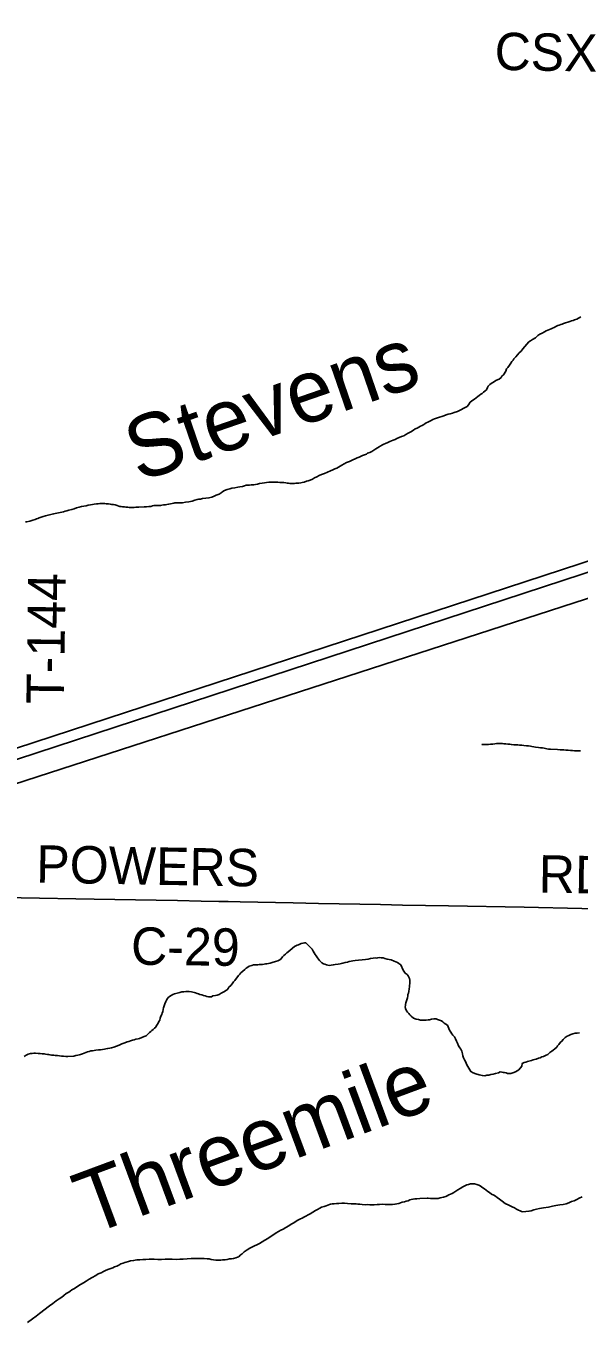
# Model space of a CAD drawing. Extents: x -483 to 680, y 0 to 440.
# Drawn here: x 79.4 to 121.3, y 248.8 to 347.1 of the extents above; entities that cross this region are included whole.
import ezdxf

# ---------------------------------------------------------------- set-up
doc = ezdxf.new("R2010")
doc.units = 0
for name, color, linetype in [('GM_X_County_Road', 7, 'Continuous'), ('GM_X_County_Road_Text', 7, 'Continuous'), ('GM_X_Minor_River', 7, 'Continuous'), ('GM_X_Minor_River_Text', 7, 'Continuous'), ('GM_X_Rail_Line', 7, 'Continuous'), ('GM_X_Rail_Line_Text', 7, 'Continuous'), ('GM_X_Township_Road_Text', 7, 'Continuous'), ('GM_X_US_Route', 7, 'Continuous')]:
    doc.layers.add(name, color=color, linetype=linetype)

msp = doc.modelspace()

# ---------------------------------------------------------------- linework, layer by layer
at = {"layer": 'GM_X_County_Road'}
msp.add_lwpolyline([(77.163, 281.006), (79.053, 280.972), (84.585, 280.875), (89.278, 280.783), (90.894, 280.761), (92.697, 280.726), (94.033, 280.704), (94.748, 280.692), (95.649, 280.674), (99.658, 280.588), (101.585, 280.553), (106.278, 280.468), (107.954, 280.425), (111.436, 280.37), (117.186, 280.256), (121.537, 280.166), (124.893, 280.092), (126.566, 280.056)], dxfattribs=at)
at = {"layer": 'GM_X_Minor_River'}
for points in [[(121.003, 324.791), (120.887, 324.737), (120.754, 324.702), (120.639, 324.667), (120.485, 324.614), (120.313, 324.561), (120.16, 324.508), (120.045, 324.473), (119.949, 324.438), (119.834, 324.384), (119.738, 324.348), (119.584, 324.276), (119.449, 324.204), (119.316, 324.169), (119.219, 324.115), (119.104, 324.061), (118.97, 324.007), (118.854, 323.953), (118.72, 323.881), (118.546, 323.79), (118.373, 323.7), (118.2, 323.59), (118.024, 323.424), (117.812, 323.296), (117.658, 323.186), (117.523, 323.114), (117.386, 322.946), (117.229, 322.76), (117.073, 322.594), (116.936, 322.426), (116.799, 322.278), (116.663, 322.129), (116.545, 321.98), (116.389, 321.832), (116.33, 321.739), (116.251, 321.627), (116.172, 321.515), (116.073, 321.347), (115.936, 321.179), (115.839, 321.087), (115.777, 320.899), (115.599, 320.618), (115.483, 320.507), (115.423, 320.414), (115.268, 320.304), (115.076, 320.214), (114.96, 320.141), (114.845, 320.068), (114.748, 320.013), (114.574, 319.885), (114.438, 319.756), (114.398, 319.662), (114.318, 319.493), (114.201, 319.382), (114.104, 319.308), (113.988, 319.216), (113.891, 319.162), (113.756, 319.051), (113.659, 318.978), (113.543, 318.886), (113.407, 318.776), (113.272, 318.703), (113.175, 318.611), (113.078, 318.537), (112.959, 318.35), (112.861, 318.22), (112.13, 317.84), (111.881, 317.77), (111.747, 317.717), (111.575, 317.664), (111.422, 317.63), (111.269, 317.577), (111.096, 317.524), (110.924, 317.472), (110.751, 317.4), (110.541, 317.33), (110.368, 317.277), (110.253, 317.223), (110.118, 317.151), (109.965, 317.079), (109.868, 317.024), (109.753, 316.97), (109.657, 316.916), (109.56, 316.842), (109.445, 316.788), (109.329, 316.734), (109.194, 316.643), (109.06, 316.589), (108.925, 316.517), (108.79, 316.425), (108.578, 316.298), (108.385, 316.189), (108.212, 316.098), (108.058, 316.007), (107.885, 315.935), (107.712, 315.864), (107.52, 315.793), (107.386, 315.72), (107.251, 315.667), (107.117, 315.613), (107.002, 315.559)], [(121.464, 325.007), (121.175, 324.843), (121.003, 324.791)], [(107.002, 315.559), (106.848, 315.487), (106.675, 315.416), (106.541, 315.362), (106.426, 315.308), (106.272, 315.217), (106.175, 315.163), (106.059, 315.09), (105.924, 314.998), (105.789, 314.907), (105.635, 314.816), (105.481, 314.744), (105.308, 314.672), (105.212, 314.618), (104.924, 314.511), (104.809, 314.457), (104.674, 314.384), (104.521, 314.331), (104.367, 314.259), (104.176, 314.188), (103.945, 314.061), (103.695, 313.973), (103.522, 313.863), (103.349, 313.773), (103.233, 313.7), (103.098, 313.627), (102.963, 313.555), (102.828, 313.482), (102.675, 313.41), (102.483, 313.339), (102.271, 313.231), (102.041, 313.141), (101.811, 313.052), (101.638, 312.981), (101.465, 312.89), (101.292, 312.8), (101.119, 312.709), (100.946, 312.638), (100.812, 312.584), (100.678, 312.55), (100.486, 312.479), (100.353, 312.463), (100.238, 312.428), (100.086, 312.413), (99.952, 312.397), (99.857, 312.4), (99.762, 312.383), (99.591, 312.387), (99.496, 312.39), (99.401, 312.392), (99.307, 312.414), (99.212, 312.416), (99.099, 312.438), (98.947, 312.461), (98.815, 312.464), (98.644, 312.469), (98.511, 312.472), (98.397, 312.475), (98.283, 312.478), (98.169, 312.481), (98.017, 312.485), (97.827, 312.489), (97.313, 312.408), (97.103, 312.375), (96.95, 312.341), (96.816, 312.306), (96.683, 312.291), (96.588, 312.293), (96.493, 312.277), (96.359, 312.261), (96.207, 312.246), (96.112, 312.248), (95.978, 312.195), (95.825, 312.161), (95.634, 312.128), (95.462, 312.094), (95.253, 312.061), (95.024, 312.029), (94.852, 311.977), (94.661, 311.925), (94.469, 311.853), (94.334, 311.781), (94.198, 311.67), (94.044, 311.579), (93.833, 311.49), (93.679, 311.418), (93.488, 311.347), (93.277, 311.295), (93.049, 311.263), (92.782, 311.232), (92.629, 311.198), (92.496, 311.182), (92.4, 311.165), (92.209, 311.113), (92.017, 311.042), (91.75, 310.992), (91.502, 310.96), (91.274, 310.928), (90.704, 310.905), (90.608, 310.888), (90.494, 310.872)], [(90.494, 310.872), (90.36, 310.838), (90.226, 310.803), (90.093, 310.788), (89.997, 310.771), (89.826, 310.756), (89.712, 310.74), (89.616, 310.705), (89.369, 310.711), (89.217, 310.715), (89.122, 310.717), (89.008, 310.682), (88.874, 310.648), (88.721, 310.633), (88.55, 310.618), (88.379, 310.622), (87.961, 310.595), (87.827, 310.579), (87.733, 310.582), (87.618, 310.566), (87.485, 310.55), (87.371, 310.553), (87.238, 310.556), (87.125, 310.578), (86.992, 310.582), (86.878, 310.604), (86.745, 310.607), (86.632, 310.629), (86.537, 310.631), (86.443, 310.672), (86.311, 310.713), (86.179, 310.754), (86.029, 310.796), (85.896, 310.799), (85.801, 310.821), (85.669, 310.843), (85.574, 310.846), (85.479, 310.848), (85.385, 310.869), (85.29, 310.872), (85.118, 310.857), (85.004, 310.86), (84.871, 310.844), (84.757, 310.828), (84.585, 310.814), (84.452, 310.779), (84.299, 310.764), (84.127, 310.73), (83.975, 310.696), (83.784, 310.663), (83.612, 310.63), (83.44, 310.596), (83.249, 310.525), (83.076, 310.472), (82.885, 310.42), (82.656, 310.369), (82.503, 310.316), (82.369, 310.281), (82.254, 310.246), (81.738, 310.126), (81.509, 310.075), (81.299, 310.043), (81.089, 309.991), (80.898, 309.939), (80.706, 309.868), (80.496, 309.816), (80.4, 309.781), (80.304, 309.726), (80.208, 309.691), (80.112, 309.655), (79.94, 309.602), (79.71, 309.532), (79.481, 309.481), (79.386, 309.465)], [(115.071, 292.658), (114.957, 292.642), (114.804, 292.627), (114.633, 292.613), (114.462, 292.598), (114.329, 292.583), (114.215, 292.585), (114.101, 292.588), (113.968, 292.592), (113.968, 292.592), (113.968, 292.592)], [(121.439, 292.115), (121.287, 292.119), (121.155, 292.122), (121.003, 292.126), (120.832, 292.131), (120.68, 292.135), (120.51, 292.158), (120.339, 292.162), (120.188, 292.185), (120.055, 292.189), (119.903, 292.193), (119.695, 292.217), (119.183, 292.249), (119.031, 292.253), (118.898, 292.275), (118.785, 292.297), (118.69, 292.319), (118.558, 292.341), (118.406, 292.345), (118.255, 292.368), (118.046, 292.392), (117.914, 292.415), (117.763, 292.437), (117.649, 292.459), (117.498, 292.482), (117.346, 292.486), (117.157, 292.51), (116.986, 292.533), (116.816, 292.538), (116.683, 292.56), (116.55, 292.564), (116.398, 292.567), (116.209, 292.591), (116.077, 292.614), (115.925, 292.618), (115.792, 292.64), (115.641, 292.644), (115.527, 292.666), (115.413, 292.669), (115.318, 292.671), (115.205, 292.674), (115.071, 292.658)], [(89.636, 272.001), (89.697, 272.132), (89.737, 272.245), (89.778, 272.339), (89.82, 272.528), (89.842, 272.622), (89.884, 272.773), (89.945, 272.943), (90.006, 273.112), (90.066, 273.224), (90.126, 273.337), (90.223, 273.429), (90.416, 273.576), (90.551, 273.649), (90.667, 273.703), (91.068, 273.806), (91.221, 273.841), (91.373, 273.856), (91.525, 273.871), (91.658, 273.867), (91.791, 273.864), (91.961, 273.841), (92.056, 273.819), (92.169, 273.797), (92.263, 273.757), (92.376, 273.716), (92.49, 273.694), (92.584, 273.654), (92.734, 273.612), (92.866, 273.571), (92.998, 273.529), (93.13, 273.488), (93.244, 273.466), (93.376, 273.463), (93.471, 273.46), (93.587, 273.533), (93.778, 273.567), (93.912, 273.601), (94.065, 273.654), (94.219, 273.745), (94.316, 273.8), (94.45, 273.872), (94.566, 273.945), (94.662, 274), (94.741, 274.093), (94.8, 274.186), (94.936, 274.316), (95.034, 274.446), (95.152, 274.595), (95.231, 274.707), (95.525, 275.079), (95.623, 275.191), (95.701, 275.284), (95.856, 275.413), (95.992, 275.542), (96.109, 275.634), (96.225, 275.726), (96.322, 275.8), (96.532, 275.851), (96.647, 275.886), (96.742, 275.884), (96.856, 275.9), (96.989, 275.897), (97.084, 275.913), (97.179, 275.911), (97.351, 275.925), (97.465, 275.941), (97.56, 275.958), (97.675, 275.974), (97.789, 275.99), (97.923, 276.025), (98.076, 276.059), (98.325, 276.147), (98.497, 276.2), (98.612, 276.254), (98.728, 276.327), (98.865, 276.494), (98.962, 276.587), (99.079, 276.698), (99.196, 276.809), (99.293, 276.882), (99.428, 276.993), (99.778, 277.288), (99.874, 277.342), (99.97, 277.378), (100.066, 277.413), (100.277, 277.503), (100.411, 277.537), (100.525, 277.553), (100.62, 277.551), (100.731, 277.453), (100.824, 277.356), (100.936, 277.258), (101.102, 277.083), (101.193, 276.929), (101.247, 276.813), (101.339, 276.678), (101.412, 276.562), (101.503, 276.427), (101.596, 276.311), (101.65, 276.214)], [(101.65, 276.214), (101.743, 276.136), (101.836, 276.039), (101.967, 275.978), (102.061, 275.938), (102.193, 275.897), (102.287, 275.875), (102.401, 275.853), (102.534, 275.869), (102.705, 275.883), (102.858, 275.918), (103.068, 275.931), (103.22, 275.965), (103.316, 276.001), (103.431, 276.017), (103.603, 276.069), (103.775, 276.103), (103.908, 276.138), (104.061, 276.172), (104.195, 276.206), (104.366, 276.221), (105.147, 276.296), (105.338, 276.329), (105.528, 276.362), (105.719, 276.395), (105.871, 276.41), (105.985, 276.407), (106.081, 276.424), (106.233, 276.439), (106.346, 276.417), (106.479, 276.414), (106.611, 276.372), (106.781, 276.33), (106.951, 276.288), (107.102, 276.265), (107.328, 276.164), (107.441, 276.123), (107.572, 276.063), (107.684, 275.984), (107.815, 275.886), (108.013, 275.482), (108.16, 275.269), (108.309, 275.151), (108.383, 275.054), (108.437, 274.958), (108.491, 274.843), (108.507, 274.728), (108.505, 274.615), (108.501, 274.482), (108.478, 274.33), (108.476, 274.217), (108.453, 274.065), (108.429, 273.876), (108.407, 273.744), (108.367, 273.65), (108.345, 273.536), (108.322, 273.385), (108.199, 273.008), (108.177, 272.895), (108.174, 272.8), (108.153, 272.705), (108.169, 272.572), (108.259, 272.399), (108.333, 272.302), (108.425, 272.205), (108.499, 272.108), (108.61, 271.991), (108.796, 271.853), (108.984, 271.773), (109.155, 271.749), (109.306, 271.707), (109.457, 271.704), (109.59, 271.7), (109.742, 271.696), (109.894, 271.711), (110.009, 271.727), (110.143, 271.762), (110.333, 271.795), (110.504, 271.791), (110.617, 271.75), (110.899, 271.647), (111.011, 271.569), (111.123, 271.471), (111.235, 271.392), (111.366, 271.313), (111.42, 271.178), (111.509, 270.948), (111.619, 270.794), (111.691, 270.659), (111.765, 270.562), (111.895, 270.445), (111.967, 270.291), (112.038, 270.099), (112.129, 269.945), (112.201, 269.753), (112.311, 269.598), (112.384, 269.501), (112.456, 269.348), (112.473, 269.252), (112.489, 269.138), (112.524, 269.004)], [(79.285, 268.941), (79.42, 269.051), (79.574, 269.123), (79.747, 269.176), (79.879, 269.172), (80.013, 269.188), (80.127, 269.185), (80.335, 269.18), (80.487, 269.176), (80.639, 269.153), (80.79, 269.149), (80.885, 269.128), (81.036, 269.105), (81.131, 269.084), (81.244, 269.062), (81.358, 269.04), (81.528, 269.036), (81.642, 269.014), (81.794, 269.01), (81.964, 268.986), (82.115, 268.964), (82.267, 268.96), (82.438, 268.936), (82.589, 268.933), (83.027, 268.959), (83.18, 269.013), (83.352, 269.046), (83.447, 269.063), (83.543, 269.098), (83.696, 269.151), (83.83, 269.186), (83.945, 269.24), (84.08, 269.294), (84.195, 269.329), (84.328, 269.363), (84.462, 269.379), (84.576, 269.395), (84.709, 269.41), (84.919, 269.443), (85.072, 269.458), (85.205, 269.474), (85.357, 269.489), (85.472, 269.524), (85.606, 269.559), (85.758, 269.574), (85.892, 269.608), (86.064, 269.661), (86.275, 269.731), (86.467, 269.803), (86.678, 269.911), (86.908, 269.981), (87.081, 270.053), (87.215, 270.087), (87.33, 270.141), (87.483, 270.176), (87.616, 270.21), (87.75, 270.245), (87.903, 270.279), (88.018, 270.314), (88.382, 270.456), (88.517, 270.51), (88.692, 270.677), (88.77, 270.769), (88.867, 270.843), (88.963, 270.917), (89.06, 270.99), (89.158, 271.101), (89.255, 271.175), (89.315, 271.287), (89.413, 271.418), (89.493, 271.606), (89.553, 271.699), (89.595, 271.85), (89.636, 272.001)], [(116.997, 268.217), (117.029, 268.414), (117.183, 268.486), (117.298, 268.521), (117.432, 268.574), (117.719, 268.643), (117.853, 268.677), (117.967, 268.712), (118.082, 268.747), (118.274, 268.819), (118.389, 268.853), (118.504, 268.908), (118.638, 268.942), (118.753, 268.996), (118.85, 269.051), (118.965, 269.105), (119.12, 269.234), (119.275, 269.344), (119.371, 269.417), (119.507, 269.527), (119.643, 269.657), (119.703, 269.75), (119.8, 269.843), (119.938, 270.029), (120.034, 270.103), (120.133, 270.233), (120.288, 270.381), (120.424, 270.472), (120.558, 270.545), (120.712, 270.617), (120.865, 270.651), (121.037, 270.704), (121.189, 270.719), (121.361, 270.733)], [(112.524, 269.004), (112.577, 268.851), (112.649, 268.678), (112.722, 268.562), (112.838, 268.309)], [(112.838, 268.309), (113.127, 267.803), (113.314, 267.702), (113.522, 267.638), (113.767, 267.554), (114.012, 267.489), (114.202, 267.482), (114.356, 267.515), (114.49, 267.53), (114.644, 267.582), (114.835, 267.613), (115.008, 267.665), (115.219, 267.715), (115.354, 267.767), (115.487, 267.763), (115.582, 267.741), (115.695, 267.718), (115.809, 267.695), (115.922, 267.653), (116.017, 267.65), (116.17, 267.664), (116.323, 267.697), (116.516, 267.785), (116.652, 267.857), (116.768, 267.929), (116.997, 268.217)], [(97.523, 255.006), (97.736, 255.133), (98.009, 255.314), (98.203, 255.44), (98.379, 255.568), (98.554, 255.676), (98.728, 255.765), (98.902, 255.855), (99.116, 255.981), (99.329, 256.107), (99.524, 256.234), (99.717, 256.341), (99.892, 256.45), (100.028, 256.54), (100.222, 256.629), (100.338, 256.682), (100.473, 256.754), (100.958, 257.023), (101.152, 257.131), (101.346, 257.257), (101.52, 257.347), (101.676, 257.456), (101.811, 257.508), (102.004, 257.578), (102.158, 257.63), (102.293, 257.682), (102.408, 257.717), (102.504, 257.751), (102.619, 257.767), (102.772, 257.781), (102.944, 257.794), (103.116, 257.807), (103.344, 257.819), (103.554, 257.812), (103.782, 257.804), (104.067, 257.776), (104.257, 257.769), (104.447, 257.763), (104.58, 257.74), (104.713, 257.735), (104.902, 257.71), (105.112, 257.703), (105.302, 257.715), (105.473, 257.691), (105.663, 257.684), (105.816, 257.698), (106.026, 257.71), (106.217, 257.723), (106.427, 257.735), (106.636, 257.728), (106.845, 257.721), (107.055, 257.733), (107.207, 257.728), (107.379, 257.741), (107.532, 257.774), (107.686, 257.807), (107.801, 257.842), (107.936, 257.894), (108.109, 257.926), (108.243, 257.979), (108.378, 258.012), (108.513, 258.065), (108.609, 258.1), (108.743, 258.114), (108.877, 258.148), (109.049, 258.161), (109.259, 258.173), (109.812, 258.193), (109.908, 258.209), (110.078, 258.184), (110.287, 258.177), (110.478, 258.171), (110.649, 258.184), (110.803, 258.217), (110.937, 258.251), (111.072, 258.284), (111.226, 258.336), (111.341, 258.389), (111.458, 258.461), (111.593, 258.514), (111.709, 258.567), (111.845, 258.639), (112, 258.729), (112.156, 258.838), (112.33, 258.946), (112.524, 259.054), (112.679, 259.144), (112.834, 259.215), (112.968, 259.248), (113.103, 259.282), (113.275, 259.295), (113.408, 259.291), (113.578, 259.247), (113.728, 259.185), (113.84, 259.124), (113.953, 259.063), (114.045, 258.984), (114.157, 258.904), (114.287, 258.805), (114.417, 258.705), (114.548, 258.625)], [(114.548, 258.625), (114.697, 258.506), (114.884, 258.423), (114.997, 258.362), (115.127, 258.263), (115.294, 258.124), (115.499, 257.984), (115.741, 257.805), (116.022, 257.662), (116.265, 257.54), (116.453, 257.458), (116.603, 257.377), (116.734, 257.296), (116.865, 257.235), (116.978, 257.193), (117.072, 257.171), (117.531, 257.212), (117.703, 257.245), (117.896, 257.314), (118.107, 257.364), (118.337, 257.414), (118.644, 257.48), (119.026, 257.524), (119.314, 257.59), (119.582, 257.639), (119.869, 257.686), (120.137, 257.734), (120.367, 257.783), (120.56, 257.853), (120.753, 257.942), (120.965, 258.011), (121.158, 258.099), (121.332, 258.189), (121.583, 258.295)], [(79.52, 248.774), (79.91, 249.065), (80.183, 249.266), (80.437, 249.467), (81.197, 250.031), (81.451, 250.213), (81.705, 250.414), (81.938, 250.577), (82.132, 250.685), (82.27, 250.833), (82.465, 250.978), (82.659, 251.086), (82.757, 251.159), (82.893, 251.25), (83.028, 251.321), (83.165, 251.412), (83.339, 251.52), (83.534, 251.647), (83.767, 251.791), (83.981, 251.917), (84.195, 252.062), (84.427, 252.188), (84.699, 252.35), (84.893, 252.458), (85.105, 252.546), (85.299, 252.654), (85.492, 252.742), (85.685, 252.812), (85.839, 252.864), (85.993, 252.916), (86.128, 252.988), (86.302, 253.058), (86.457, 253.129), (86.612, 253.219), (86.785, 253.27), (86.901, 253.323), (87.016, 253.358), (87.17, 253.41), (87.343, 253.442), (87.572, 253.472), (87.802, 253.522), (88.05, 253.533), (88.26, 253.564), (88.508, 253.556), (88.756, 253.566), (89.118, 253.573), (89.403, 253.564), (89.688, 253.554), (89.955, 253.565), (90.222, 253.575), (90.488, 253.566), (90.812, 253.555), (91.079, 253.565), (91.327, 253.576), (91.938, 253.632), (92.338, 253.638), (92.661, 253.627), (92.927, 253.618), (93.156, 253.611), (93.308, 253.606), (93.459, 253.563), (93.63, 253.538), (93.8, 253.513), (93.952, 253.508), (94.066, 253.504), (94.181, 253.5), (94.314, 253.515), (94.505, 253.528), (94.659, 253.561), (94.831, 253.593), (94.984, 253.607), (95.137, 253.64), (95.31, 253.672), (95.445, 253.725), (95.541, 253.76), (95.64, 253.87), (95.795, 253.979), (95.952, 254.126), (96.167, 254.272), (96.381, 254.417), (96.574, 254.505), (96.728, 254.576), (96.903, 254.666), (97.115, 254.754), (97.309, 254.88), (97.523, 255.006)]]:
    msp.add_lwpolyline(points, dxfattribs=at)
at = {"layer": 'GM_X_Rail_Line'}
msp.add_lwpolyline([(52.231, 281.076), (127.278, 305.392), (222.338, 336.549), (257.887, 348.093), (262.457, 349.692), (266.922, 351.391), (271.85, 353.786), (276.063, 355.851), (279.587, 357.722), (282.074, 359.273), (284.73, 360.909), (286.844, 362.348), (291.566, 365.767), (297.907, 370.986), (306.481, 378.212), (309.709, 381.296), (311.628, 383.535), (313.46, 385.542), (315.408, 389.44), (316.608, 391.805), (318.711, 395.95)], dxfattribs=at)
at = {"layer": 'GM_X_US_Route'}
for points in [[(77.288, 291.856), (122.784, 306.734), (124.838, 307.43), (126.301, 307.972), (127.421, 308.449)], [(77.267, 290.998), (123.029, 305.999), (125.191, 306.715), (126.663, 307.257), (127.389, 307.543)]]:
    msp.add_lwpolyline(points, dxfattribs=at)

# ---------------------------------------------------------------- texts
at = {"layer": 'GM_X_County_Road_Text'}
for s, rotation, p in [('POWERS', 358.98658, (80.17, 282.122)), ('RD', 359.01741, (118.258, 281.372)), ('C-29', 359.31382, (87.363, 275.904))]:
    msp.add_text(s, height=2.8409, rotation=rotation, dxfattribs=at).set_placement(p)
at = {"layer": 'GM_X_Minor_River_Text'}
for s, rotation, p in [('Stevens', 19.04053, (87.949, 312.466)), ('Threemile', 20.37047, (84.229, 255.366))]:
    msp.add_text(s, height=4.737, rotation=rotation, dxfattribs=at).set_placement(p)
at = {"layer": 'GM_X_Rail_Line_Text'}
msp.add_text('CSX', height=2.8314, rotation=358.93967, dxfattribs=at).set_placement((114.918, 343.744))
at = {"layer": 'GM_X_Township_Road_Text'}
msp.add_text('T-144', height=2.8409, rotation=89.17161, dxfattribs=at).set_placement((82.279, 295.653))

doc.saveas('drawing.dxf')
